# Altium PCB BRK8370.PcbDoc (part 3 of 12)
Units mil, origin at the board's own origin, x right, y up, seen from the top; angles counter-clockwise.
Board outline 8267.72 x 5708.66 mil, 6 copper layers (L1-TOP, L2-GND, L3-PWR, L4-PWR, L5-GND, L6-BOT), stack 68.606 mil thick; 319 components, 516 nets, 2008 pads, 1743 vias.
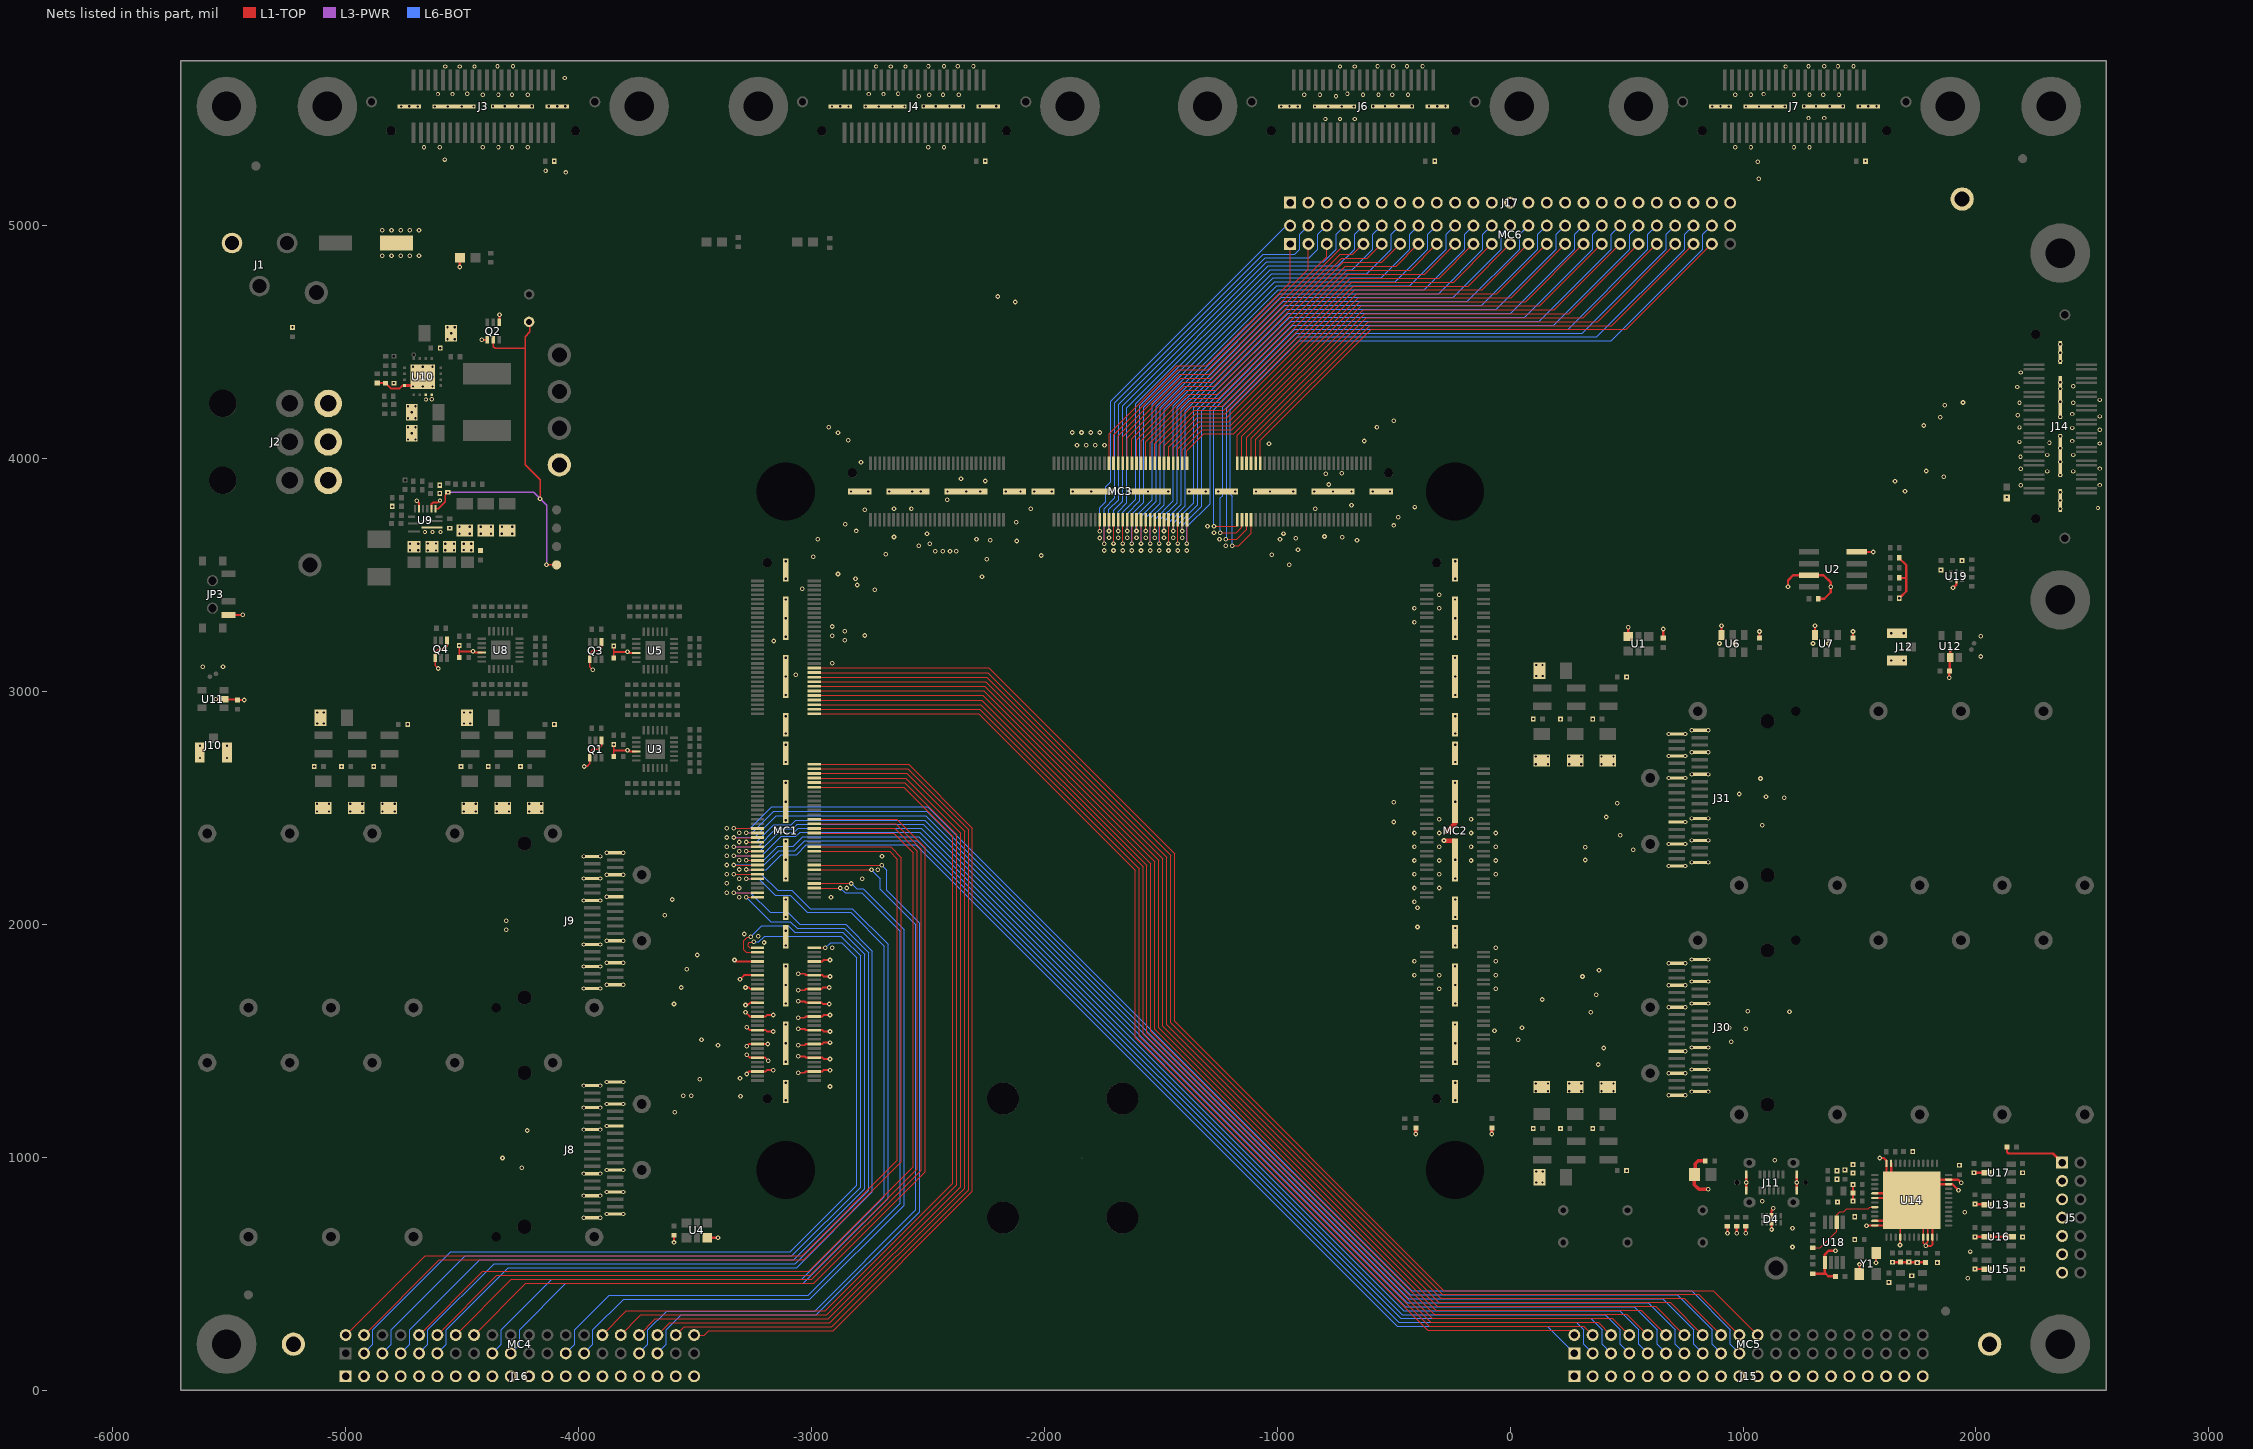
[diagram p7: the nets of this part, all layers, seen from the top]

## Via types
v1: diameter 20, hole 10, L1-TOP to L6-BOT, tented both sides, 957 vias
v2: diameter 18, hole 10, L1-TOP to L6-BOT, tented both sides, 786 vias

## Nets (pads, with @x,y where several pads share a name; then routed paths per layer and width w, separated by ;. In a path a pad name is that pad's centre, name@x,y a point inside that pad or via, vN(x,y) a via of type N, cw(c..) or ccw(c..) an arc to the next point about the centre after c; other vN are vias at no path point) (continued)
B68_L11N: MC1.96 MC4.16 | length 4145.3
  L1-TOP w4.96: MC4.16@-4448.82,236.22 -4226.79,458.25 -2991.04,458.25 -2512.19,937.1 -2512.19,2328.34 -2634.64,2450.79 -2935.44,2450.79 MC1.96@-2988.58,2450.79
B68_L11P: MC1.94 MC4.14 | length 4173.7
  L1-TOP w4.96: MC4.14@-4527.56,236.22 -4288.57,475.21 -2998.07,475.21 -2529.15,944.13 -2529.15,2321.31 -2638.94,2431.1 -2935.44,2431.1 MC1.94@-2988.58,2431.1
B68_L12N: MC1.92 MC4.12 | length 4202.2
  L1-TOP w4.96: MC4.12@-4606.3,236.22 -4350.35,492.17 -3005.09,492.17 -2546.12,951.15 -2546.12,2314.29 -2643.25,2411.42 -2935.44,2411.42 MC1.92@-2988.58,2411.42
B68_L12P: MC1.90 MC4.10 | length 4230.6
  L1-TOP w4.96: MC4.10@-4685.04,236.22 -4412.12,509.14 -3012.12,509.14 -2563.08,958.18 -2563.08,2307.26 -2647.55,2391.73 -2935.44,2391.73 MC1.90@-2988.58,2391.73
B68_L13N: MC1.84 MC4.4 | length 4315.9
  L1-TOP w4.96: MC4.4@-4921.26,236.22 -4597.46,560.02 -3033.2,560.02 -2613.97,979.26 -2613.97,2286.18 -2660.46,2332.68 -2935.44,2332.68 MC1.84@-2988.58,2332.68
B68_L13P: MC1.82 MC4.2 | length 4344.3
  L1-TOP w4.96: MC4.2@-5000,236.22 -4659.23,576.99 -3040.23,576.99 -2630.93,986.28 -2630.93,2279.15 -2664.77,2312.99 -2935.44,2312.99 MC1.82@-2988.58,2312.99
B68_L14N: MC1.91 MC5.19 | length 5468.2
  L1-TOP w4.96: v1(-3333.92,2412.11) -3333.22,2411.42 MC1.91@-3231.89,2411.42 MC1.91@-3231.62,2411.69
  L6-BOT w4.96: v1(-3333.92,2412.11) -3262.99,2412.11 -3170.83,2504.27 -2499.71,2504.27 -421.5,426.07 778.99,426.07 946.06,259.01 946.06,195.67 MC5.19@984.25,157.48
B68_L14P: MC1.89 MC5.17 | length 5273.4
  L1-TOP w4.96: v1(-3280.05,2392.54) -3279.78,2392.27 -3231.89,2392.27 MC1.89@-3231.62,2392
  L6-BOT w4.96: v1(-3280.05,2392.54) -3255,2392.54 -3162.95,2484.59 -2504.01,2484.59 -428.53,409.11 717.22,409.11 867.32,259.01 867.32,195.67 MC5.17@905.51,157.48
B68_L15N: MC1.76 MC4.35 | length 3261.7
  L1-TOP w4.96: MC1.76@-2988.58,2253.94 v1(-2698.82,2253.94)
  L6-BOT w4.96: MC4.35@-3661.42,157.48 -3623.22,195.67 -3623.22,259.01 -3559.97,322.26 -2978.59,322.26 -2534.46,766.38 -2534.46,2004.91 -2676.29,2146.73 -2676.29,2231.41 v1(-2698.82,2253.94)
B68_L15P: MC1.74 MC4.33 | length 3266.5
  L1-TOP w4.96: MC1.74@-2988.58,2234.25 -2743.38,2234.25 v1(-2742.51,2233.38)
  L6-BOT w4.96: MC4.33@-3740.16,157.48 -3701.96,195.67 -3701.96,259.01 -3621.75,339.22 -2985.61,339.22 -2551.43,773.41 -2551.43,1997.88 -2704.72,2151.18 -2704.72,2195.59 v1(-2742.51,2233.38)
B68_L16N: MC1.75 MC5.3 | length 4782.2
  L1-TOP w4.96: v1(-3333.92,2254.63) -3333.22,2253.94 MC1.75@-3231.89,2253.94 MC1.75@-3231.62,2254.21
  L6-BOT w4.96: v1(-3333.92,2254.63) -3202.06,2254.63 -3141.07,2315.63 -3070.93,2315.63 -3028.77,2357.79 -2545.13,2357.79 -477.71,290.37 284.78,290.37 316.14,259.01 316.14,195.67 MC5.3@354.33,157.48
B68_L16P: MC1.73 MC5.1 | length 4552.5
  L1-TOP w4.96: v1(-3280.05,2235.06) -3279.78,2234.79 -3231.89,2234.79 MC1.73@-3231.62,2234.52
  L6-BOT w4.96: v1(-3280.05,2235.06) -3194.07,2235.06 -3129.92,2299.21 -3064.13,2299.21 -3022.52,2340.82 -2935.44,2340.82 -2552.16,2340.82 -484.74,273.41 159.66,273.41 MC5.1@275.59,157.48
B68_L17N: MC1.63 MC4.11 | length 4029.5
  L1-TOP w4.96: v1(-3333.92,2135.98) -3333.22,2135.29 -3231.89,2135.29 MC1.63@-3231.62,2135.56
  L6-BOT w4.96: MC4.11@-4606.3,157.48 -4568.11,195.67 -4568.11,259.01 -4301.3,525.81 -3062.9,525.81 -2738.02,850.7 -2738.02,1885.16 -2852.42,1999.56 -2852.79,1999.56 -2852.94,1999.71 -3050.89,1999.71 -3102.36,2051.18 -3177.17,2051.18 -3261.97,2135.98 v1(-3333.92,2135.98)
B68_L17P: MC1.61 MC4.9 | length 3950
  L1-TOP w4.96: v1(-3280.05,2116.41) -3279.78,2116.14 MC1.61@-3231.89,2116.14 MC1.61@-3231.62,2115.87
  L6-BOT w4.96: MC4.9@-4685.04,157.48 -4646.85,195.67 -4646.85,259.01 -4363.08,542.78 -3069.93,542.78 -2754.98,857.72 -2754.98,1878.13 -2859.45,1982.59 -2859.81,1982.59 -2859.96,1982.74 -3061.48,1982.74 -3090.55,2011.81 -3175.45,2011.81 v1(-3280.05,2116.41)
B68_L18N: MC1.68 MC4.27 | length 3325.8
  L1-TOP w4.96: MC1.68@-2988.58,2175.2 v1(-2828.74,2175.2)
  L6-BOT w4.96: MC4.27@-3976.38,157.48 -3938.18,195.67 -3938.18,259.01 -3807.08,390.11 -3006.69,390.11 -2602.32,794.48 -2602.32,1976.8 -2719.3,2093.79 -2777.84,2152.33 -2805.87,2152.33 v1(-2828.74,2175.2)
B68_L18P: MC1.66 MC4.25 | length 3354.2
  L1-TOP w4.96: MC1.66@-2988.58,2155.51 v1(-2875.98,2155.51)
  L6-BOT w4.96: MC4.25@-4055.12,157.48 -4016.93,195.67 -4016.93,259.01 -3868.86,407.07 -3013.72,407.07 -2619.28,801.51 -2619.28,1969.78 -2726.33,2076.82 -2784.87,2135.37 -2855.84,2135.37 v1(-2875.98,2155.51)
B68_L19N: MC1.79 MC5.7 | length 4954.7
  L1-TOP w4.96: v1(-3333.92,2294) -3333.22,2293.31 MC1.79@-3231.89,2293.31 MC1.79@-3231.62,2293.58
  L6-BOT w4.96: v1(-3333.92,2294) -3213.87,2294 -3130.3,2377.58 -3066.97,2377.58 -3048.89,2395.65 -2535.02,2395.65 -463.66,324.3 408.33,324.3 473.62,259.01 473.62,195.67 MC5.7@511.81,157.48
B68_L19P: MC1.77 MC5.5 | length 4760.6
  L1-TOP w4.96: v1(-3280.05,2274.43) -3279.78,2274.16 -3231.89,2274.16 MC1.77@-3231.62,2273.89
  L6-BOT w4.96: v1(-3280.05,2274.43) -3205.88,2274.43 -3145.67,2334.65 -3078.81,2334.65 -3036.65,2376.81 -2540.16,2376.81 -470.69,307.33 346.69,307.33 394.88,259.15 394.88,195.67 MC5.5@433.07,157.48
B68_L20N: MC1.83 MC5.11 | length 5124
  L1-TOP w4.96: v1(-3333.92,2333.37) -3333.22,2332.68 MC1.83@-3231.89,2332.68 MC1.83@-3231.62,2332.95
  L6-BOT w4.96: v1(-3333.92,2333.37) -3229.36,2333.37 -3152.65,2410.08 -3080.43,2410.08 -3060.93,2429.58 -2520.97,2429.58 -449.61,358.22 531.88,358.22 631.1,259.01 631.1,195.67 MC5.11@669.29,157.48
B68_L20P: MC1.81 MC5.9 | length 4931.4
  L1-TOP w4.96: v1(-3280.05,2313.8) -3279.78,2313.53 -3231.89,2313.53 MC1.81@-3231.62,2313.26
  L6-BOT w4.96: v1(-3280.05,2313.8) -3221.58,2313.8 -3140.49,2394.89 -3074.14,2394.89 -3056.41,2412.62 -2527.99,2412.62 -456.64,341.26 470.11,341.26 552.36,259.01 552.36,195.67 MC5.9@590.55,157.48
B68_L22N: MC1.71 MC4.19 | length 3916
  L1-TOP w4.96: v1(-3333.92,2215.26) -3333.22,2214.57 MC1.71@-3231.89,2214.57 MC1.71@-3231.62,2214.84
  L6-BOT w4.96: MC4.19@-4291.34,157.48 -4253.15,195.67 -4253.15,259.01 -4054.19,457.96 -3034.8,457.96 -2670.17,822.59 -2670.17,1913.26 -2824.46,2067.56 -3006.3,2067.56 -3084.41,2145.67 -3145.67,2145.67 -3215.26,2215.26 v1(-3333.92,2215.26)
B68_L22P: MC1.69 MC4.17 | length 3836.6
  L1-TOP w4.96: v1(-3280.05,2195.69) -3279.78,2195.42 -3231.89,2195.42 MC1.69@-3231.62,2195.15
  L6-BOT w4.96: MC4.17@-4370.08,157.48 -4331.89,195.67 -4331.89,259.01 -4115.97,474.92 -3041.82,474.92 -2687.13,829.62 -2687.13,1906.24 -2831.49,2050.6 -3018.12,2050.6 -3091.3,2123.78 -3155.28,2123.78 -3227.19,2195.69 v1(-3280.05,2195.69)
B68_L23N: MC1.87 MC5.15 | length 5294.4
  L1-TOP w4.96: v1(-3333.92,2372.74) -3333.22,2372.05 MC1.87@-3231.89,2372.05 MC1.87@-3231.62,2372.32
  L6-BOT w4.96: v1(-3333.92,2372.74) -3243.3,2372.74 -3151.14,2464.9 -2508.31,2464.9 -2448.92,2405.51 -435.56,392.15 655.44,392.15 788.58,259.01 788.58,195.67 MC5.15@826.77,157.48
B68_L23P: MC1.85 MC5.13 | length 5100.7
  L1-TOP w4.96: v1(-3280.05,2353.17) -3279.78,2352.9 -3231.89,2352.9 MC1.85@-3231.62,2352.63
  L6-BOT w4.96: v1(-3280.05,2353.17) -3236.69,2353.17 -3162.99,2426.86 -3087.38,2426.86 -3067.7,2446.54 -2513.94,2446.54 -442.58,375.18 593.66,375.18 709.84,259.01 709.84,195.67 MC5.13@748.03,157.48
B68_T0U_N12_VRP: MC1.59 MC4.5 | length 3963.8
  L1-TOP w4.96: v1(-3247.56,1924.77) -3250,1922.32 -3266.66,1922.32 -3271.65,1917.32 -3271.65,1905.51 -3265.75,1899.61 MC1.59@-3231.89,1899.61
  L6-BOT w4.96: MC4.5@-4842.52,157.48 -4804.33,195.67 -4804.33,259.01 -4486.63,576.7 -3083.98,576.7 -2788.91,871.77 -2788.91,1864.08 -2863.05,1938.22 -2863.42,1938.22 -2874.02,1948.82 -3201.6,1948.82 -3225.65,1924.77 v1(-3247.56,1924.77)
B68_T1U_N12: MC1.57 MC4.7 | length 4027.5
  L1-TOP w4.96: v1(-3261.32,1945.8) -3262.02,1945.1 -3275.37,1945.1 -3291.3,1929.17 -3291.3,1890.71 -3280.52,1879.92 MC1.57@-3231.89,1879.92
  L6-BOT w4.96: MC4.7@-4763.78,157.48 -4725.59,195.67 -4725.59,259.01 -4424.85,559.74 -3076.95,559.74 -2771.95,864.75 -2771.95,1871.11 -2866.47,1965.63 -2866.84,1965.63 -2866.99,1965.78 -3072.08,1965.78 -3100.01,1993.71 -3213.41,1993.71 v1(-3261.32,1945.8)
B68_T2U_N12: MC1.60 MC4.3 | length 3648.6
  L1-TOP w4.96: MC1.60@-2988.85,1899.34 -2988.58,1899.07 -2940.69,1899.07 v1(-2940.42,1898.8)
  L6-BOT w4.96: MC4.3@-4921.26,157.48 -4883.07,195.67 -4883.07,259.01 -4548.41,593.67 -3091.01,593.67 -2805.87,878.8 -2805.87,1857.05 -2870.08,1921.26 -2917.96,1921.26 v1(-2940.42,1898.8)
B69_L3P: MC1.142 MC5.22 | length 5659.3
  L1-TOP w4.96: MC1.142@-2988.58,3100.39 -2238.45,3100.39 -1440.61,2302.55 -1440.61,1583.34 -284.56,427.29 871.92,427.29 MC5.22@1062.99,236.22
B69_L5N: MC1.136 MC5.16 | length 5398.6
  L1-TOP w4.96: MC1.136@-2988.58,3041.34 -2251.37,3041.34 -1491.5,2281.47 -1491.5,1562.26 -305.64,376.4 686.59,376.4 MC5.16@826.77,236.22
B69_L5P: MC1.134 MC5.14 | length 5311.7
  L1-TOP w4.96: MC1.134@-2988.58,3021.65 -2255.67,3021.65 -1508.46,2274.44 -1508.46,1555.23 -312.66,359.44 624.82,359.44 MC5.14@748.03,236.22
B69_L11N: MC1.128 MC5.8 | length 5051
  L1-TOP w4.96: MC1.128@-2988.58,2962.6 -2935.44,2962.6 -2268.58,2962.6 -1559.35,2253.36 -1559.35,1534.15 -333.74,308.55 439.48,308.55 MC5.8@511.81,236.22
B69_L11P: MC1.126 MC5.6 | length 4964.1
  L1-TOP w4.96: MC1.126@-2988.58,2942.91 -2935.44,2942.91 -2272.89,2942.91 -1576.31,2246.34 -1576.31,1527.13 -340.77,291.58 377.71,291.58 MC5.6@433.07,236.22
B69_L14N: MC1.112 MC4.32 | length 3917.9
  L1-TOP w4.96: MC4.32@-3818.9,236.22 -3732.58,322.54 -2934.83,322.54 -2376.49,880.89 -2376.49,2384.55 -2600.2,2608.27 -2935.44,2608.27 MC1.112@-2988.58,2608.27
B69_L14P: MC1.110 MC4.30 | length 3946.3
  L1-TOP w4.96: MC4.30@-3897.64,236.22 -3794.35,339.51 -2941.86,339.51 -2393.45,887.91 -2393.45,2377.52 -2604.51,2588.58 -2935.44,2588.58 MC1.110@-2988.58,2588.58
B69_L16N: MC1.116 MC4.36 | length 3861
  L1-TOP w4.96: MC4.36@-3661.42,236.22 -3609.02,288.62 -2920.78,288.62 -2342.56,866.84 -2342.56,2398.6 -2591.6,2647.64 -2935.44,2647.64 MC1.116@-2988.58,2647.64
B69_L16P: MC1.114 MC4.34 | length 3889.4
  L1-TOP w4.96: MC4.34@-3740.16,236.22 -3670.8,305.58 -2927.81,305.58 -2359.52,873.86 -2359.52,2391.58 -2595.9,2627.95 -2935.44,2627.95 MC1.114@-2988.58,2627.95
B69_L20N: MC1.140 MC5.20 | length 5572.4
  L1-TOP w4.96: MC1.140@-2988.58,3080.71 -2242.76,3080.71 -1457.57,2295.52 -1457.57,1576.31 -291.58,410.33 810.15,410.33 MC5.20@984.25,236.22
B69_L20P: MC1.138 MC5.18 | length 5485.5
  L1-TOP w4.96: MC1.138@-2988.58,3061.02 -2247.06,3061.02 -1474.53,2288.49 -1474.53,1569.29 -298.61,393.36 748.37,393.36 MC5.18@905.51,236.22
B69_L21N: MC1.124 MC5.4 | length 4877.2
  L1-TOP w4.96: MC1.124@-2988.58,2923.23 -2935.44,2923.23 -2277.19,2923.23 -1593.27,2239.31 -1593.27,1520.1 -347.79,274.62 315.93,274.62 MC5.4@354.33,236.22
B69_L21P: MC1.122 MC5.2 | length 4790.3
  L1-TOP w4.96: MC1.122@-2988.58,2903.54 -2935.44,2903.54 -2281.5,2903.54 -1610.24,2232.28 -1610.24,1513.07 -354.82,257.66 254.15,257.66 MC5.2@275.59,236.22
B69_L23N: MC1.120 MC4.40 | length 3804.2
  L1-TOP w4.96: MC4.40@-3503.94,236.22 -3460.63,236.22 -3442.16,254.69 -2906.73,254.69 -2308.63,852.78 -2308.63,2412.65 -2582.99,2687.01 -2935.44,2687.01 MC1.120@-2988.58,2687.01
B69_L23P: MC1.118 MC4.38 | length 3832.6
  L1-TOP w4.96: MC4.38@-3582.68,236.22 -3547.24,271.65 -2913.75,271.65 -2325.6,859.81 -2325.6,2405.63 -2587.29,2667.32 -2935.44,2667.32 MC1.118@-2988.58,2667.32
B69_L24N: MC1.132 MC5.12 | length 5224.8
  L1-TOP w4.96: MC1.132@-2988.58,3001.97 -2259.98,3001.97 -1525.42,2267.41 -1525.42,1548.21 -319.69,342.47 563.04,342.47 MC5.12@669.29,236.22
B69_L24P: MC1.130 MC5.10 | length 5137.9
  L1-TOP w4.96: MC1.130@-2988.58,2982.28 -2264.28,2982.28 -1542.38,2260.39 -1542.38,1541.18 -326.71,325.51 501.26,325.51 MC5.10@590.55,236.22
B88_L1N: MC3.104 MC6.24 | length 2475
  L1-TOP w4.96: v1(-1545.43,3634.59) -1544.74,3635.28 -1544.74,3736.61 MC3.104@-1545.01,3736.88
  L6-BOT w4.96: v1(-1545.43,3634.59) -1545.43,3742.34 -1485.99,3801.78 -1485.99,4211.13 -1310.17,4386.95 -988.79,4708.32 -323.65,4708.32 -307.08,4708.32 -116.93,4898.47 -116.93,4961.81 MC6.24@-78.74,5000
B88_L1P: MC3.102 MC6.22 | length 2310.6
  L1-TOP w4.96: v1(-1565.23,3688.45) -1564.96,3688.72 MC3.102@-1564.96,3736.61 MC3.102@-1564.69,3736.88
  L6-BOT w4.96: v1(-1565.23,3688.45) -1565.23,3746.53 -1502.95,3808.81 -1502.95,4218.16 -995.82,4725.29 -385.42,4725.29 -368.86,4725.29 -195.67,4898.47 -195.67,4961.81 MC6.22@-157.48,5000
B88_L2N: MC3.87 MC6.3 | length 1362.4
  L1-TOP w4.96: MC3.87@-1702.76,3979.92 -1702.76,4055.12 -1702.76,4102.33 -1425.04,4380.05 -1297.85,4380.05 -866.14,4811.76 MC6.3@-866.14,4921.26
B88_L2P: MC3.85 MC6.1 | length 1337.9
  L1-TOP w4.96: MC3.85@-1722.44,3979.92 -1722.44,4055.12 -1722.44,4106.64 -1431.44,4397.64 -1304.25,4397.64 -944.88,4757.01 MC6.1@-944.88,4921.26
B88_L3N: MC3.103 MC6.19 | length 1750.5
  L1-TOP w4.96: MC3.103@-1545.28,3979.92 -1545.28,4067.9 -1371.17,4242 -1243.98,4242 -694.56,4791.43 -366.05,4791.43 MC6.19@-236.22,4921.26
B88_L3P: MC3.101 MC6.17 | length 1694
  L1-TOP w4.96: MC3.101@-1564.96,3979.92 -1564.96,4072.2 -1378.2,4258.97 -1251.01,4258.97 -701.59,4808.39 -427.83,4808.39 MC6.17@-314.96,4921.26
B88_L4N: MC3.95 MC6.11 | length 1524.4
  L1-TOP w4.96: MC3.95@-1624.02,3979.92 -1624.02,4085.12 -1399.28,4309.86 -1272.09,4309.86 -722.66,4859.28 -613.16,4859.28 MC6.11@-551.18,4921.26
B88_L4P: MC3.93 MC6.9 | length 1467.8
  L1-TOP w4.96: MC3.93@-1643.7,3979.92 -1643.7,4055.12 -1643.7,4089.42 -1406.3,4326.82 -1279.11,4326.82 -729.69,4876.24 -674.94,4876.24 MC6.9@-629.92,4921.26
B88_L5N: MC3.99 MC6.15 | length 1637.4
  L1-TOP w4.96: MC3.99@-1584.65,3979.92 -1584.65,4076.51 -1385.22,4275.93 -1258.03,4275.93 -708.61,4825.35 -489.61,4825.35 MC6.15@-393.7,4921.26
B88_L5P: MC3.97 MC6.13 | length 1569.8
  L1-TOP w4.96: MC3.97@-1601.61,3992.13 -1604.33,3994.85 -1604.33,4080.81 -1392.25,4292.89 -1265.06,4292.89 -715.64,4842.32 -551.39,4842.32 MC6.13@-472.44,4921.26
B88_L6N: MC3.91 MC6.7 | length 1411.3
  L1-TOP w4.96: MC3.91@-1663.39,3979.92 -1663.39,4055.12 -1663.39,4093.72 -1413.33,4343.78 -1286.14,4343.78 MC6.7@-708.66,4921.26
B88_L6P: MC3.89 MC6.5 | length 1386.8
  L1-TOP w4.96: MC3.89@-1683.07,3979.92 -1683.07,4055.12 -1683.07,4098.03 -1418.89,4362.2 -1291.71,4362.2 -787.4,4866.51 MC6.5@-787.4,4921.26
B88_L7N: MC3.84 MC6.4 | length 1910
  L1-TOP w4.96: v1(-1742.55,3634.32) -1741.86,3635.01 -1741.86,3736.34 MC3.84@-1742.13,3736.61
  L6-BOT w4.96: v1(-1742.55,3634.32) -1742.55,3785.11 -1697.15,3830.52 -1697.15,4239.86 -1059.06,4877.95 -924.86,4877.95 -904.33,4898.47 -904.33,4961.81 MC6.4@-866.14,5000
B88_L7P: MC3.82 MC6.2 | length 1708.5
  L1-TOP w4.96: v1(-1762.35,3688.18) -1762.08,3688.45 -1762.08,3736.34 MC3.82@-1761.81,3736.61
  L6-BOT w4.96: v1(-1762.35,3688.18) -1762.35,3789.3 -1736.57,3815.08 -1736.57,3879.22 -1714.65,3901.14 -1714.65,4055.12 -1714.65,4246.34 -969.84,4991.16 -953.73,4991.16 MC6.2@-944.88,5000
B88_L8N: MC3.107 MC6.23 | length 1863.6
  L1-TOP w4.96: MC3.107@-1505.91,3979.92 -1505.91,4059.29 -1357.12,4208.08 -1229.93,4208.08 -680.51,4757.5 -242.5,4757.5 MC6.23@-78.74,4921.26
B88_L8P: MC3.105 MC6.21 | length 1807
  L1-TOP w4.96: MC3.105@-1525.59,3979.92 -1525.59,4063.59 -1364.14,4225.04 -1236.96,4225.04 -687.53,4774.46 -304.28,4774.46 MC6.21@-157.48,4921.26
B88_L9N: MC3.92 MC6.12 | length 2135.8
  L1-TOP w4.96: v1(-1663.54,3634.59) -1662.85,3635.28 -1662.85,3736.61 MC3.92@-1663.12,3736.88
  L6-BOT w4.96: v1(-1663.54,3634.59) -1663.54,3768.16 -1606.53,3825.18 -1606.53,4234.52 -1030.95,4810.1 -677.75,4810.1 -589.37,4898.47 -589.37,4961.81 MC6.12@-551.18,5000
B88_L9P: MC3.90 MC6.10 | length 1971.4
  L1-TOP w4.96: v1(-1683.34,3688.45) -1683.07,3688.72 MC3.90@-1683.07,3736.61 MC3.90@-1682.8,3736.88
  L6-BOT w4.96: v1(-1683.34,3688.45) -1683.34,3772.35 -1646.26,3809.44 -1646.26,4218.78 -1037.98,4827.06 -739.52,4827.06 -668.11,4898.47 -668.11,4961.81 MC6.10@-629.92,5000
B88_L10N: MC3.96 MC6.16 | length 2248.8
  L1-TOP w4.96: v1(-1624.17,3634.59) -1623.48,3635.28 -1623.48,3736.61 MC3.96@-1623.75,3736.88
  L6-BOT w4.96: v1(-1624.17,3634.59) -1624.17,3759.55 -1572.6,3811.13 -1572.6,4220.47 -1016.9,4776.17 -554.19,4776.17 -431.89,4898.47 -431.89,4961.81 MC6.16@-393.7,5000
B88_L10P: MC3.94 MC6.14 | length 2084.4
  L1-TOP w4.96: v1(-1643.97,3688.45) -1643.7,3688.72 MC3.94@-1643.7,3736.61 MC3.94@-1643.43,3736.88
  L6-BOT w4.96: v1(-1643.97,3688.45) -1643.97,3763.75 -1589.56,3818.15 -1589.56,4227.5 -1023.92,4793.14 -615.97,4793.14 -510.63,4898.47 -510.63,4961.81 MC6.14@-472.44,5000
B88_L11N: MC3.88 MC6.8 | length 2022.7
  L1-TOP w4.96: v1(-1702.91,3634.59) -1702.22,3635.28 -1702.22,3736.61 MC3.88@-1702.49,3736.88
  L6-BOT w4.96: v1(-1702.91,3634.59) -1702.91,3776.77 -1663.22,3816.46 -1663.22,4225.81 -1045,4844.03 -801.3,4844.03 -746.85,4898.47 -746.85,4961.81 MC6.8@-708.66,5000
B88_L11P: MC3.86 MC6.6 | length 1858.3
  L1-TOP w4.96: v1(-1722.71,3688.45) -1722.44,3688.72 MC3.86@-1722.44,3736.61 MC3.86@-1722.17,3736.88
  L6-BOT w4.96: v1(-1722.71,3688.45) -1722.71,3780.96 -1680.18,3823.49 -1680.18,4232.84 -1052.03,4860.99 -863.08,4860.99 -825.59,4898.47 -825.59,4961.81 MC6.6@-787.4,5000
B88_L12N: MC3.100 MC6.20 | length 2361.9
  L1-TOP w4.96: v1(-1584.8,3634.59) -1584.11,3635.28 -1584.11,3736.61 MC3.100@-1584.38,3736.88
  L6-BOT w4.96: v1(-1584.8,3634.59) -1584.8,3750.95 -1519.91,3815.84 -1519.91,4225.18 -1002.84,4742.25 -430.64,4742.25 -274.41,4898.47 -274.41,4961.81 MC6.20@-236.22,5000
B88_L12P: MC3.98 MC6.18 | length 2197.5
  L1-TOP w4.96: v1(-1604.6,3688.45) -1604.33,3688.72 MC3.98@-1604.33,3736.61 MC3.98@-1604.06,3736.88
  L6-BOT w4.96: v1(-1604.6,3688.45) -1604.6,3755.14 -1536.87,3822.86 -1536.87,4232.21 -1009.87,4759.21 -492.42,4759.21 -353.15,4898.47 -353.15,4961.81 MC6.18@-314.96,5000
B89_L1N: MC3.112 MC6.32 | length 2701.1
  L1-TOP w4.96: v1(-1466.69,3634.59) -1466,3635.28 -1466,3736.61 MC3.112@-1466.27,3736.88
  L6-BOT w4.96: v1(-1466.69,3634.59) -1466.69,3725.12 -1395.43,3796.38 -1395.43,4205.72 -1315.63,4285.53 -960.69,4640.47 -76.54,4640.47 -59.97,4640.47 198.03,4898.47 198.03,4961.81 MC6.32@236.22,5000
B89_L1P: MC3.110 MC6.30 | length 2536.7
  L1-TOP w4.96: v1(-1486.49,3688.45) -1486.22,3688.72 MC3.110@-1486.22,3736.61 MC3.110@-1485.95,3736.88
  L6-BOT w4.96: v1(-1486.49,3688.45) -1486.49,3729.31 -1412.4,3803.4 -1412.4,4212.75 -1335.82,4289.33 -1274.18,4350.97 -967.71,4657.43 -138.31,4657.43 -121.75,4657.43 119.29,4898.47 119.29,4961.81 MC6.30@157.48,5000
B89_L2N: MC3.108 MC6.28 | length 2588
  L1-TOP w4.96: v1(-1506.06,3634.59) -1505.37,3635.28 -1505.37,3736.61 MC3.108@-1505.64,3736.88
  L6-BOT w4.96: v1(-1506.06,3634.59) -1506.06,3733.73 -1429.36,3810.43 -1429.36,4219.78 -1348.81,4300.33 -974.74,4674.4 -200.09,4674.4 -183.53,4674.4 40.55,4898.47 40.55,4961.81 MC6.28@78.74,5000
B89_L2P: MC3.106 MC6.26 | length 2423.6
  L1-TOP w4.96: v1(-1525.86,3688.45) -1525.59,3688.72 MC3.106@-1525.59,3736.61 MC3.106@-1525.32,3736.88
  L6-BOT w4.96: v1(-1525.86,3688.45) -1525.86,3737.92 -1446.32,3817.46 -1446.32,4226.8 -1353.37,4319.76 -981.77,4691.36 -261.87,4691.36 -245.31,4691.36 -38.19,4898.47 -38.19,4961.81 MC6.26@0,5000
B89_L3N: MC3.116 MC6.36 | length 2814.2
  L1-TOP w4.96: v1(-1427.32,3634.59) -1426.63,3635.28 -1426.63,3736.61 MC3.116@-1426.9,3736.88
  L6-BOT w4.96: v1(-1427.32,3634.59) -1427.32,3716.51 -1341.53,3802.3 -1341.53,4211.65 -1256.83,4296.35 -946.63,4606.54 63.58,4606.54 355.51,4898.47 355.51,4961.81 MC6.36@393.7,5000
B89_L3P: MC3.114 MC6.34 | length 2649.8
  L1-TOP w4.96: v1(-1447.12,3688.45) -1446.85,3688.72 MC3.114@-1446.85,3736.61 MC3.114@-1446.58,3736.88
  L6-BOT w4.96: v1(-1447.12,3688.45) -1444.42,3691.15 -1444.42,3723.4 -1358.49,3809.33 -1358.49,4218.67 -1281.32,4295.84 -953.66,4623.51 -14.76,4623.51 1.8,4623.51 276.77,4898.47 276.77,4961.81 MC6.34@314.96,5000
B89_L4N: MC3.120 MC6.40 | length 2927.2
  L1-TOP w4.96: v1(-1387.95,3634.59) -1387.26,3635.28 -1387.26,3736.61 MC3.120@-1387.53,3736.88
  L6-BOT w4.96: v1(-1387.95,3634.59) -1387.95,3706.54 -1288.62,3805.87 -1288.62,4216.58 -932.58,4572.62 170.57,4572.62 187.13,4572.62 512.99,4898.47 512.99,4961.81 MC6.40@551.18,5000
B89_L4P: MC3.118 MC6.38 | length 2762.8
  L1-TOP w4.96: v1(-1407.75,3688.45) -1407.48,3688.72 MC3.118@-1407.48,3736.61 MC3.118@-1407.21,3736.88
  L6-BOT w4.96: v1(-1407.75,3688.45) -1407.75,3711.36 -1324.57,3794.54 -1324.57,4204.62 -939.61,4589.58 108.79,4589.58 125.36,4589.58 434.25,4898.47 434.25,4961.81 MC6.38@472.44,5000
B89_L5N: MC3.128 MC6.48 | length 3177.3
  L1-TOP w4.96: v1(-1192.91,3625.98) -1166.21,3625.98 -1112.2,3679.99 MC3.128@-1112.2,3736.61
  L6-BOT w4.96: v1(-1192.91,3625.98) -1192.91,3838.58 -1200.79,3846.46 -1200.79,4208.46 -904.48,4504.77 434.24,4504.77 827.95,4898.47 827.95,4961.81 MC6.48@866.14,5000
B89_L5P: MC3.126 MC6.46 | length 3077
  L1-TOP w4.96: v1(-1220.47,3653.54) -1174.39,3653.54 -1131.89,3696.04 MC3.126@-1131.89,3736.61
  L6-BOT w4.96: v1(-1220.47,3653.54) -1217.75,3656.27 -1217.75,4215.48 -1178.22,4255.01 -911.5,4521.73 372.47,4521.73 749.21,4898.47 749.21,4961.81 MC6.46@787.4,5000
B89_L6N: MC3.127 MC6.43 | length 2272.9
  L1-TOP w4.96: MC3.127@-1112.2,3979.92 -1112.2,4085.91 -610.24,4587.87 375.27,4587.87 MC6.43@708.66,4921.26
B89_L6P: MC3.125 MC6.41 | length 2216.3
  L1-TOP w4.96: MC3.125@-1131.89,3979.92 -1131.89,4090.21 -617.27,4604.83 313.49,4604.83 MC6.41@629.92,4921.26
B89_L7N: MC3.115 MC6.31 | length 2089.7
  L1-TOP w4.96: MC3.115@-1427.17,3979.92 -1427.17,4042.07 -1414.12,4055.12 -1329.01,4140.23 -1201.82,4140.23 -652.4,4689.65 4.61,4689.65 MC6.31@236.22,4921.26
B89_L7P: MC3.113 MC6.29 | length 2033.2
  L1-TOP w4.96: MC3.113@-1446.85,3979.92 -1446.85,4046.38 -1438.11,4055.12 -1336.04,4157.19 -1208.85,4157.19 -659.43,4706.61 -57.17,4706.61 MC6.29@157.48,4921.26
B89_L8N: MC3.119 MC6.35 | length 2202.8
  L1-TOP w4.96: MC3.119@-1387.8,3979.92 -1387.8,4033.46 -1366.14,4055.12 -1314.96,4106.3 -1187.77,4106.3 -638.35,4655.72 128.16,4655.72 MC6.35@393.7,4921.26
B89_L8P: MC3.117 MC6.33 | length 2146.2
  L1-TOP w4.96: MC3.117@-1407.48,3979.92 -1407.48,4037.77 -1390.13,4055.12 -1321.99,4123.26 -1194.8,4123.26 -645.37,4672.69 66.39,4672.69 MC6.33@314.96,4921.26
B89_L9N: MC3.131 MC6.47 | length 2385.9
  L1-TOP w4.96: MC3.131@-1072.83,3979.92 -1072.83,4077.3 -596.19,4553.94 498.83,4553.94 MC6.47@866.14,4921.26
B89_L9P: MC3.129 MC6.45 | length 2329.4
  L1-TOP w4.96: MC3.129@-1092.52,3979.92 -1092.52,4081.6 -603.22,4570.91 437.05,4570.91 MC6.45@787.4,4921.26
B89_L10N: MC3.123 MC6.39 | length 2159.8
  L1-TOP w4.96: MC3.123@-1151.58,3979.92 -1151.58,4094.52 -624.3,4621.8 251.72,4621.8 MC6.39@551.18,4921.26
B89_L10P: MC3.121 MC6.37 | length 2103.3
  L1-TOP w4.96: MC3.121@-1171.26,3979.92 -1171.26,4098.82 -631.32,4638.76 189.94,4638.76 MC6.37@472.44,4921.26
B89_L11N: MC3.111 MC6.27 | length 1976.6
  L1-TOP w4.96: MC3.111@-1466.54,3979.92 -1466.54,4050.68 -1462.1,4055.12 -1343.07,4174.15 -1215.88,4174.15 -666.45,4723.57 -118.95,4723.57 MC6.27@78.74,4921.26
B89_L11P: MC3.109 MC6.25 | length 1920.1
  L1-TOP w4.96: MC3.109@-1486.22,3979.92 -1486.22,4054.99 -1486.09,4055.12 -1350.09,4191.11 -1222.9,4191.11 -673.48,4740.54 -180.72,4740.54 MC6.25@0,4921.26
B89_L12N: MC3.124 MC6.44 | length 2981.9
  L1-TOP w4.96: v1(-1244.09,3681.1) -1175.45,3681.1 -1151.58,3704.98 MC3.124@-1151.58,3736.61
  L6-BOT w4.96: v1(-1244.09,3681.1) -1244.09,3830.71 -1234.71,3840.09 -1234.71,4222.51 -918.53,4538.69 310.69,4538.69 670.47,4898.47 670.47,4961.81 MC6.44@708.66,5000
B89_L12P: MC3.122 MC6.42 | length 2892.2
  L1-TOP w4.96: v1(-1271.65,3708.66) -1176.58,3708.66 -1171.26,3713.98 MC3.122@-1171.26,3736.61
  L6-BOT w4.96: v1(-1271.65,3708.66) -1271.65,4209.56 -925.56,4555.66 232.35,4555.66 248.91,4555.66 591.73,4898.47 591.73,4961.81 MC6.42@629.92,5000
BRK8370_PGOOD: Q2.5 R72.1 TP18.1 TP22.1 U9.7 | length 1810.9
  L1-TOP w6: U9.7@-4614.32,3784.66 -4603.07,3784.66 -4572.65,3815.08 -4572.65,3842.49 -4569.65,3845.49 -4569.65,3847.46 -4562.81,3854.3 v2(-4560.84,3854.3) ; Q2.5@-4366.14,4509.84 -4366.14,4480.32 -4358.27,4472.44 -4228.35,4472.44 ; TP22.1@-4212.6,4586.61 -4208.66,4582.68 -4208.66,4543.31 -4228.35,4523.62 -4228.35,4472.44 ; v1(-4165.42,3826.67) -4165.42,3909.52 -4228.35,3972.44 -4228.35,4472.44 ; v1(-4137.8,3543.31) TP18.1@-4094.49,3543.31
  L3-PWR w6: v2(-4560.84,3854.3) -4193.05,3854.3 -4137.8,3799.04 v1(-4137.8,3543.31)
DGND: C1.2 C2.2 C3.1 C4.1 C5.1 C6.1 C7.1 C8.1 C9.1 C10.1 C11.1 C12.1 C13.1 C14.1 C15.1 C16.1 C17.1 C18.1 C19.1 C20.1 C21.1 C22.1 C23.1 C24.1 C25.1 C26.1 C27.1 C28.2 C29.1 C30.1 C31.1 C32.1 C33.1 C34.1 C35.1 C36.1 C37.1 C38.1 C41.1 C42.1 C43.1 C44.1 C45.1 C46.1 C47.1 C48.1 C49.1 C50.1 C51.1 C52.1 C55.1 C56.1 C57.1 C58.1 C59.1 C60.1 C61.1 C62.1 C63.1 C64.1 C65.1 C66.1 C67.1 C68.1 C69.1 C70.1 C71.1 C72.1 C73.1 C74.1 C75.1 C76.1 C77.1 C78.1 C79.1 C80.1 C81.1 C82.1 C90.1 C91.1 C92.1 C93.1 C94.1 C95.1 C102.1 C103.1 C104.1 C105.1 C106.1 C107.1 C111.1 C112.1 C113.1 C114.1 C128.1 C129.1 D1.1 D4.3 D4.8 FB4.2 J1.2 J2.4 J2.5 J2.6 J3.0 J4.0 J5.1 J5.3 J5.5 J5.7 J5.9 J5.11 J5.13 J6.0 J7.0 J8.1 J8.4 J8.7 J8.13 J8.16 J8.19 J8.20 J8.23 J8.26 J8.32 J8.35 J8.38 J9.1 J9.4 J9.7 J9.13 J9.16 J9.19 J9.20 J9.23 J9.26 J9.32 J9.35 J9.38 J10.2 J11.A1 J11.A12 J11.B1 J11.B12 J12.2 J14.0 J15.1 J15.2 J15.3 J15.4 J15.5 J15.6 J15.7 J15.8 J15.9 J15.10 J15.11 J15.12 J15.13 J15.14 J15.15 J15.16 J15.17 J15.18 J15.19 J15.20 J16.1 J16.2 J16.3 J16.4 J16.5 J16.6 J16.7 J16.8 J16.9 J16.10 J16.11 J16.12 J16.13 J16.14 J16.15 J16.16 J16.17 J16.18 J16.19 J16.20 J17.1 J17.2 J17.3 J17.4 J17.5 J17.6 J17.7 J17.8 J17.9 J17.10 J17.11 J17.12 J17.13 J17.14 J17.15 J17.16 J17.17 J17.18 J17.19 J17.20 J17.21 J17.22 J17.23 J17.24 J17.25 J30.1 J30.4 J30.7 J30.13 J30.16 J30.19 J30.20 J30.23 J30.26 J30.32 J30.35 J30.38 J31.1 J31.4 J31.7 J31.13 J31.16 J31.19 J31.20 J31.23 J31.26 J31.32 J31.35 J31.38 JP3.3 MC1.0 MC1.5 MC1.6 MC1.11 MC1.12 MC1.17 MC1.18 MC1.23 MC1.24 MC1.29 MC1.30 MC1.35 MC1.36 MC1.41 MC1.42 MC1.47 MC1.48 MC1.53 MC1.54 MC2.0 MC3.0 MC6.50 Q1.1 Q1.4 Q2.1 Q2.4 Q3.1 Q3.4 Q4.1 Q4.4 R7.1 R8.1 R9.1 R10.1 R11.1 R27.1 R66.1 R67.1 R70.1 R73.1 R78.1 R93.1 R94.2 R95.1 R97.2 R98.2 R99.2 R101.1 TP10.1 TP11.1 TP12.1 TP13.1 U1.3 U2.4 U2.7 U3.22 U4.3 U5.22 U6.3 U7.3 U8.22 U9.4 U9.8 U9.11 U10.4 U10.7 U10.8 U10.PAD U11.2 U12.2 U13.2 U14.4 U14.9 U14.10 U14.11 U14.22 U14.23 U14.35 U14.36 U14.41 U14.42 U14.47 U14.48 U14.PAD U15.2 U16.2 U16.5 U17.2 U18.5 U19.4 Y1.2 Y1.4 | length 8566.2
  L1-TOP w7: v1(-4602.36,3098.43) -4616.14,3112.2 Q4.4@-4616.14,3143.7 -4616.14,3167.32 -4602.36,3181.1 -4578.74,3181.1 -4564.96,3194.88 Q4.1@-4564.96,3218.5 ; v1(-3976.38,2677.17) -3974.79,2678.76 -3962.98,2678.76 -3952.76,2688.98 -3952.76,2738.19 -3938.98,2751.97 -3915.35,2751.97 -3901.57,2765.75 Q1.1@-3901.57,2789.37 ; v1(-3938.98,3092.52) -3952.76,3106.3 Q3.4@-3952.76,3137.8 -3952.76,3161.42 -3938.98,3175.2 -3915.35,3175.2 -3901.57,3188.98 Q3.1@-3901.57,3212.6
  L1-TOP w8: JP3.3@-5502.23,3328.48 v1@-5443.36,3328.48 ; R78.1@-4865.25,4324.18 C55.1@-4829.65,4324.18 ; C55.1@-4829.25,4323.79 C55.1@-4828.86,4323.39 -4805.33,4299.87 -4770.02,4299.87 -4756.89,4312.99 U10.4@-4747.05,4312.99 ; C32.1@-4512.2,3145.67 -4512.2,3171.26 ; v1(-4512.2,3196.85) -4512.2,3171.26 ; v1(-4415.98,4509.39) -4392.18,4509.39 Q2.4@-4391.73,4509.84 ; U8.22@-4415.35,3167.32 -4445.81,3167.32 -4450.21,3171.72 v1(-4453.46,3171.72) -4511.75,3171.72 -4512.2,3171.26 ; Q2.1@-4340.55,4584.65 -4340.2,4585 -4340.2,4616.99 v1(-4339.85,4617.34) ; C5.1@-3848.82,2720.47 -3848.82,2746.06 ; v1(-3848.82,2771.65) -3848.82,2746.06 ; C30.1@-3848.82,3143.7 -3848.82,3169.29 ; v1(-3848.82,3194.88) -3848.82,3169.29 ; U3.22@-3751.97,2742.13 -3782.43,2742.13 -3786.83,2746.52 v1(-3790.07,2746.52) -3848.36,2746.52 -3848.82,2746.06 ; U5.22@-3751.97,3165.35 -3782.43,3165.35 -3786.83,3169.75 v1(-3790.07,3169.75) -3848.36,3169.75 -3848.82,3169.29 ; v1(-3330.71,1846.46) -3324.8,1840.55 MC1.53@-3231.89,1840.55 ; v1(-3307.09,1763.78) -3289.37,1781.5 MC1.47@-3231.89,1781.5 ; v1(-3283.46,1622.05) -3265.75,1604.33 -3196.67,1604.33 -3190.97,1610.04 v1(-3163.56,1610.04) ; v1(-3283.46,1653.54) -3281.17,1655.84 -3270.52,1655.84 -3262.97,1663.39 MC1.35@-3231.89,1663.39 ; v1(-3283.46,1728.35) -3268.88,1728.35 -3262.97,1722.44 MC1.41@-3231.89,1722.44 ; v1(-3278.24,1356.98) -3267.11,1368.11 MC1.5@-3231.89,1368.11 -3196.67,1368.11 -3190.97,1373.82 v1(-3163.56,1373.82) ; v1@-3278.24,1475.09 -3267.11,1486.22 MC1.17@-3231.89,1486.22 -3231.62,1485.95 -3187.41,1485.95 v1(-3187.14,1485.68) ; v1(-3278.09,1439.5) -3265.75,1427.17 MC1.11@-3231.89,1427.17 -3198.82,1427.17 v1(-3185.04,1413.39) ; v1@-3277.68,1557.21 -3265.75,1545.28 MC1.23@-3231.89,1545.28 -3196.67,1545.28 -3190.97,1539.57 v1(-3163.56,1539.57) ; v1(-3056.92,1362.4) -3029.51,1362.4 -3023.8,1368.11 MC1.6@-2988.58,1368.11 -2953.37,1368.11 -2947.66,1373.82 v1(-2920.25,1373.82) ; v1(-3056.92,1432.87) -3029.51,1432.87 -3023.8,1427.17 MC1.12@-2988.58,1427.17 -2953.37,1427.17 -2947.66,1421.46 v1(-2920.25,1421.46) ; v1(-3056.92,1480.51) -3029.51,1480.51 -3023.8,1486.22 MC1.18@-2988.58,1486.22 -2953.37,1486.22 -2947.66,1491.93 v1(-2920.25,1491.93) ; v1(-3056.92,1550.98) -3029.51,1550.98 -3023.8,1545.28 MC1.24@-2988.58,1545.28 -2953.37,1545.28 -2947.66,1539.57 v1(-2920.25,1539.57) ; v1(-3056.92,1598.62) -3029.51,1598.62 -3023.8,1604.33 MC1.30@-2988.58,1604.33 -2953.37,1604.33 -2947.66,1610.04 v1(-2920.25,1610.04) ; v1(-3056.92,1669.09) -3029.51,1669.09 -3023.8,1663.39 MC1.36@-2988.58,1663.39 ; v1(-3056.92,1716.73) -3029.51,1716.73 -3023.8,1722.44 MC1.42@-2988.58,1722.44 -2957.5,1722.44 -2951.79,1728.15 v1(-2924.38,1728.15) ; v1(-3056.92,1787.2) -3029.51,1787.2 -3023.8,1781.5 MC1.48@-2988.58,1781.5 -2953.37,1781.5 -2947.66,1775.79 v1(-2920.25,1775.79) ; MC1.36@-2992.72,1663.39 -2957.5,1663.39 -2951.79,1657.68 v1(-2924.38,1657.68) ; MC1.54@-2988.58,1840.55 -2953.37,1840.55 -2947.66,1846.26 v1(-2920.25,1846.26) ; v1(1673.8,622.47) 1674.84,623.52 1674.84,656.14 U14.4@1675.2,656.5 U14.PAD@1675.2,765.75 ; U14.PAD@1724.41,814.96 U14.PAD@1773.62,765.75 ; U14.PAD@1773.62,765.75 U14.PAD@1793.31,746.06 ; U14.PAD@1773.62,765.75 U14.9@1773.62,656.5 1773.62,631.33 v1(1785.05,619.9) ; v1(1785.05,619.9) 1787.35,622.19 1787.35,630.23 1793.31,636.19 U14.10@1793.31,656.5 U14.PAD@1793.31,746.06 ; v1(1785.05,619.9) 1786.84,618.11 1807.09,618.11 1812.99,624.02 U14.11@1812.99,656.5 1812.99,726.38 U14.PAD@1793.31,746.06
  L1-TOP w9: v1(-4694.7,3818.87) -4694.7,3817.37 -4685.19,3807.87 U9.11@-4685.19,3784.66 ; U9.8@-4632.04,3784.66 -4632.04,3804.24 -4624.76,3811.53 -4603.23,3811.53 v2(-4595.17,3819.59)
  L1-TOP w10: v1(-5558.21,2966.57) U11.2@-5522.77,2966.57 -5521,2964.8 -5465.49,2964.8 -5463.52,2962.83 -5436.35,2962.83 v1(-5436.16,2962.63) ; C55.1@-4829.65,4324.18 C55.1@-4829.25,4323.79 ; D1.1@-4509.84,4862.2 D1.1@-4509.84,4862.2 v1(-4509.78,4822.42) ; v1(-3590.55,633.86) C34.1@-3590.55,664.57 ; U4.3@-3447.83,653.54 v1(-3401.57,653.54) ; U1.3@506.89,3236.22 v1(506.89,3275.59) ; C6.1@657.48,3228.74 v1(657.48,3268.11) ; U6.3@907.48,3242.13 v1(907.48,3281.5) ; v1(933.07,673.23) R97.2@933.07,702.76 ; v1(972.44,673.23) R98.2@972.44,702.76 ; v1(1011.81,673.23) R99.2@1011.81,702.76 ; J11.A12@1013.78,856.89 J11.B1@1013.78,925 ; C51.1@1070.87,3228.74 v1(1070.87,3256.8) ; D4.8@1122.05,717.22 1122.34,716.93 1122.34,689.33 v1(1122.64,689.03) ; D4.3@1122.05,747.24 1122.39,747.59 1122.39,769.71 1130.49,777.8 v1(1130.49,780.51) ; v1(1192.91,3448.82) 1192.91,3476.38 1215.16,3498.62 U2.7@1283.46,3498.62 1345.81,3498.62 1377.31,3467.12 v1@1377.31,3448.62 ; J11.A1@1230.32,856.89 J11.B12@1230.32,925 ; R101.1@1299.21,500 1348.43,500 1351.38,502.95 ; U7.3@1309.06,3242.13 v1(1309.06,3281.5) ; C4.1@1323.23,3397.64 1349.07,3397.64 1376.72,3425.29 v1(1376.72,3448.62) ; v1(1396.91,598.14) 1367.44,598.14 1351.38,582.07 U18.5@1351.38,547.24 1351.38,502.95 ; C82.1@1397.24,488.19 1366.14,488.19 1351.38,502.95 ; v1(1472.05,811.02) C67.1@1472.05,846.46 v1(1472.05,881.89) ; C52.1@1472.44,3228.74 v1(1472.44,3256.8) ; U2.4@1488.19,3598.62 v1(1558.86,3598.62) ; Y1.2@1499.02,498.03 1500,499.02 v1(1500,539.37) ; v1(1529.87,706.05) 1530.43,706.61 1565.87,706.61 U14.48@1565.94,706.69 1616.14,706.69 U14.PAD@1635.83,726.38 ; U14.47@1565.94,726.38 U14.PAD@1635.83,726.38 ; U14.42@1565.94,824.8 U14.PAD@1714.57,824.8 ; U14.41@1565.94,844.49 U14.PAD@1694.88,844.49 ; v1(1570.87,547.24) 1570.87,587.6 Y1.4@1571.85,588.58 ; v1(1586.61,996.06) 1604.17,996.06 1616.14,984.09 U14.36@1616.14,973.43 1616.14,923.23 U14.PAD@1631.89,907.48 ; U14.35@1635.83,973.43 1635.83,911.42 U14.PAD@1631.89,907.48 ; v1(1641.73,548.82) 1642.52,548.03 1782.68,548.03 C57.1@1783.46,547.24 ; v1(1671.23,3400.36) 1671.23,3402.33 1676.07,3407.17 1678.04,3407.17 1700.79,3429.92 1700.79,3488.19 ; R8.1@1671.23,3486.98 1699.57,3486.98 1700.79,3488.19 ; R7.1@1671.23,3573.59 1671.23,3571.62 1700.79,3542.06 1700.79,3488.19 ; v1(1885.83,3059.06) 1886.02,3059.25 1886.02,3086.42 C8.1@1886.22,3086.61 1887.99,3088.39 1887.99,3143.9 U12.2@1889.76,3145.67 v1(1889.76,3181.1) ; v1(1901.73,3444.29) 1916.34,3458.9 U19.4@1916.34,3471.46 ; v1(1925.2,858.27) 1899.61,883.86 U14.22@1882.87,883.86 U14.PAD@1793.31,883.86 ; v1(1937.01,889.76) 1923.23,903.54 U14.23@1882.87,903.54 1812.99,903.54 U14.PAD@1793.31,883.86 ; v1(1992.13,932.68) 1992.32,932.87 2045.08,932.87 U17.2@2045.28,933.07 ; v1(1996.06,519.69) U15.2@2045.28,519.69 ; v1(1996.06,657.48) U16.2@2045.28,657.48 U16.5@2151.57,657.48 U16.5@2151.77,657.28 ; v1(1996.06,798.82) 1997.83,797.05 2043.5,797.05 U13.2@2045.28,795.28 ; C27.1@2133.86,1043.31 2133.86,1021.61 2139.72,1015.75 2330.71,1015.75 J5.1@2370.08,976.38 ; C75.1@2200.59,657.28 v1(2200.79,657.09) ; U14.PAD@1631.89,907.48 U14.PAD@1694.88,844.49 ; U14.PAD@1635.83,726.38 1675.2,765.75 U14.PAD@1724.41,814.96 ; U14.PAD@1694.88,844.49 U14.PAD@1714.57,824.8 ; U14.PAD@1714.57,824.8 U14.PAD@1724.41,814.96 ; U14.PAD@1724.41,814.96 U14.PAD@1793.31,883.86
  L1-TOP w13: U10.4@-4747.05,4312.99 -4714.91,4312.99 v2(-4711.29,4309.38)
  L1-TOP w15: JP3.3@-5502.92,3327.78 JP3.3@-5502.23,3328.48 ; v1@-5443.36,3328.48 v1(-5442.67,3329.17) ; v1(-404.74,1099.2) C1.2@-404.74,1125.59 ; v1(-78.74,1099.2) C2.2@-78.74,1125.59 ; C77.1@838.19,984.25 807.09,984.25 795.28,972.44 795.28,929.13 FB4.2@791.34,925.2 791.34,881.89 811.02,862.2 v1(850.39,862.2)
  L1-TOP w20: v1(-283.77,2359.46) -283.4,2359.09 -238.82,2359.09 -236.22,2356.5 v1(-236.22,2276.57) ; v1(-271.65,2397.64) -236.22,2433.07 v1(-236.22,2526.57)
  other v1: 1625.98,462.2 1964.57,480.31 1724.41,490.55 2200.79,519.29 1748.03,547.24 1834.65,547.24 1712.6,549.61 1976.38,594.49 1212.6,614.17 1479.92,645.67 1212.51,694.46 1479.92,744.09 1952.76,763.78 2200.79,794.88 1405.91,807.09 1082.68,811.02 1013.78,890.94 1230.32,890.94 1403.54,905.51 1472.05,932.09 2200.79,932.68 1403.54,940.94 500.18,942.03 1437.01,945.28 -4244.6,954.78 1929.13,964.96 1472.05,967.52 1135.66,987.32 -4326.77,996.06 1728.74,1023.62 -4220.47,1114.17 -3586.61,1192.91 -3110.24,1244.09 -236.22,1244.09 -3304.83,1262.13 -3551.18,1263.78 -3515.75,1263.78 -2920.25,1303.35 -3110.24,1318.9 -236.22,1318.9 -3480.32,1334.65 -3307.09,1338.58 377.95,1397.64 -3110.24,1409.45 -236.22,1409.45 401.57,1468.5 -3278.52,1475.54 -3401.57,1480.32 -3110.24,1489.17 -236.22,1489.17 948.82,1496.06 -3472.44,1503.94 35.43,1503.94 -66.93,1543.31 1011.81,1551.18 51.18,1555.12 940.94,1555.12 -3277.96,1557.66 -3110.46,1569.72 -236.45,1569.72 346.46,1622.05 1199.39,1624.24 1019.68,1625.98 -3590.55,1657.48 -3110.24,1659.45 -236.22,1659.45 137.8,1677.17 370.08,1696.85 -304.74,1722.49 -61.44,1722.49 -3559.06,1728.35 -3110.24,1739.17 -236.22,1739.17 311.02,1775.59 -411.01,1781.45 -304.74,1781.55 -61.44,1781.55 381.89,1803.15 -3535.43,1807.09 -3110.46,1819.72 -236.45,1819.72 -61.44,1840.6 -411.01,1841.03 -3490.82,1868.23 -2911.03,1898.8 -61.44,1899.66 -3110.24,1909.06 -236.22,1909.06 -3203.51,1921.35 -3228.35,1948.82 -3289.28,1958.42 -3110.24,1972.44 -236.22,1983.86 -397.64,1988.19 -4311.02,2015.75 -3110.24,2031.5 -236.22,2031.5 -3629.92,2039.37 -397.64,2070.87 -411.01,2096.41 -3598.43,2106.3 -3110.24,2106.3 -236.22,2106.3 -3309.45,2116.41 -2916.13,2116.21 -3363.31,2135.98 -2849.04,2155.51 -411.01,2155.46 -304.74,2155.56 -3309.45,2155.78 -3363.31,2175.89 -3309.45,2195.69 -2782.12,2194.88 -3110.24,2196.85 -236.22,2196.85 -411.01,2214.62 -304.74,2214.62 -61.44,2214.62 -3363.31,2215.26 -2715.57,2233.38 -3309.45,2235.06 -3363.31,2254.63 -411.01,2273.67 -304.74,2273.57 -167.7,2273.57 -61.44,2273.67 -3309.45,2274.43 322.83,2275.59 -3110.24,2276.57 -2696.85,2291.34 -3363.31,2294 -3309.45,2313.8 527.96,2319.6 322.83,2330.71 -411.01,2332.73 -167.7,2332.63 -61.44,2332.73 -3363.31,2333.37 -304.74,2333.15 -3309.45,2353.17 -3110.46,2357.12 -3363.31,2372.74 472.44,2381.89 -304.74,2391.68 -167.7,2391.68 -3309.45,2392.54 -411.01,2391.78 -61.44,2391.78 -3363.31,2412.11 1082.68,2425.2 -500.06,2439.01 -3110.24,2446.85 -304.74,2450.74 -167.7,2450.74 413.39,2460.63 460.63,2519.68 -500,2523.62 -3110.24,2526.57 1177.17,2543.31 1098.43,2547.24 984.25,2559.06 -3110.46,2607.12 -236.45,2607.12 1074.8,2625.98 -3110.24,2696.46 -236.22,2696.46 -5625.98,2713.8 -5509.84,2713.8 -5625.98,2766.51 -5509.84,2766.51 -3110.24,2771.26 -236.22,2771.26 -3110.24,2818.9 -236.22,2818.9 -3110.24,2893.7 -236.22,2893.7 -3110.24,2984.25 -236.22,2984.25 500.18,3061.91 -3110.24,3063.98 -236.22,3063.98 -3068.03,3071.75 -5613.32,3105.69 -5526.7,3105.69 -2911.03,3120.89 1637,3132.74 1689.71,3132.74 -3110.46,3144.52 -236.45,3144.52 2020.64,3149.5 898.91,3205.7 965.27,3205.7 1300.48,3205.7 1366.84,3205.7 -3161.42,3216.54 -2857.16,3219.2 -3110.24,3234.25 -236.22,3234.25 2020.64,3236.12 -2911.03,3239 -2771.65,3240.16 1637,3248.88 1689.71,3248.88 -2857.16,3258.57 -2911.03,3278.37 -411.01,3297.19 -3110.24,3313.98 -236.22,3313.98 -304.74,3356.35 -411.01,3356.78 -3110.46,3394.52 -236.45,3394.52 -304.74,3415.4 -2728.35,3437.01 -3039.37,3440.94 -2803.15,3456.69 -3110.24,3483.86 -2811.02,3484.25 -236.22,3483.86 -2267.72,3492.13 -2885.83,3503.94 1849.21,3521.26 -948.82,3543.31 -3110.24,3558.66 -236.22,3558.66 1940.16,3561.02 -2248.03,3566.93 -2991.92,3577.7 -2013.92,3583.51 -1023.62,3586.61 -2681.1,3588.99 -2468.5,3602.36 -2437.01,3602.36 -2405.51,3602.36 -2377.95,3602.36 -1742.55,3604.92 -1702.91,3605.19 -1663.54,3605.19 -1624.17,3605.19 -1584.8,3605.19 -1545.43,3605.19 -1506.06,3605.19 -1466.69,3605.19 -1427.32,3605.19 -1387.95,3605.19 -910.88,3608.6 -2539.37,3625.98 -1220.47,3625.98 -2492.13,3633.86 -2118.11,3645.67 -2232.28,3649.61 -657.48,3649.61 -2972.44,3653.54 -2291.34,3653.54 -1248.03,3653.54 -988.19,3653.54 -921.26,3657.48 -1762.35,3658.79 -1722.71,3659.06 -1683.34,3659.06 -1643.97,3659.06 -1604.6,3659.06 -1565.23,3659.06 -1525.86,3659.06 -1486.49,3659.06 -1447.12,3659.06 -1407.75,3659.06 -720.47,3661.42 -2645.8,3662.66 -797.06,3665.08 -2503.94,3677.17 -972.98,3677.52 -1271.65,3681.1 -2807.09,3688.98 -1299.21,3708.66 -500,3712.6 -2855.04,3717.11 -2120.15,3726.64 -480.32,3748.03 -2771.65,3779.53 -2645.67,3783.46 -2570.87,3783.46 -2059.06,3783.46 -837.34,3784.63 -409.45,3791.34 -4799.88,3793.94 -681.1,3799.21 -2417.32,3822.83 -2830.32,3858.27 -2755.91,3858.27 -2666.18,3858.04 -2566.93,3858.27 -2531.5,3858.27 -2416.18,3858.04 -2335.63,3858.27 -2275.59,3858.27 -2165.35,3858.27 -2102.36,3858.27 -2042.91,3858.27 -1968.11,3858.27 -1878.78,3858.04 -1798.23,3858.27 -1718.5,3858.27 -1628.78,3858.04 -1555.12,3858.27 -1468.5,3858.27 -1377.95,3858.27 -1307.09,3858.27 -1253.41,3858.13 -1180.71,3858.27 -1091.37,3858.04 -1031.5,3858.27 -931.1,3858.27 -841.37,3858.04 -760.83,3858.27 -681.1,3858.27 -590.55,3858.27 -515.75,3858.27 1695.84,3859.27 -778.53,3888.48 1652.54,3902.58 -2253.94,3903.6 -2358.27,3913.39 1861.89,3921.84 -791.06,3934.8 -722.86,3936 1787.32,3945.94 -2787.4,3984.25 -1859.97,4057.48 -1820.6,4057.48 -1781.23,4057.48 -1741.86,4057.48 -1035.43,4062.99 -625.98,4074.8 -2842.52,4078.74 -2885.83,4110.24 -1879.77,4111.34 -1840.4,4111.34 -1801.03,4111.34 -1761.66,4111.34 -2925.2,4133.86 -572.02,4134.75 1775.59,4141.73 -500,4161.42 1846.46,4177.17 1866.14,4228.35 1944.88,4240.16 -5228.35,4562.99 -2124.94,4672.18 -2199.74,4695.81 -4842.52,4870.08 -4803.15,4870.08 -4763.78,4870.08 -4724.41,4870.08 -4685.04,4870.08 -4842.52,4980.32 -4803.15,4980.32 -4763.78,4980.32 -4724.41,4980.32 -4685.04,4980.32 1066.93,5200.79 -4055.12,5228.35 -4141.73,5236.22 1062.99,5274.59 -4574.8,5283.46
  other v2: -3977.59,740.16 -3906.66,740.16 -3878.77,755.91 -3807.84,755.91 -3977.59,834.65 -3906.66,834.65 -3878.77,850.39 -3807.84,850.39 111.99,890.85 139.16,890.85 -3977.59,929.13 -3906.66,929.13 111.99,938.09 139.55,938.09 -3878.77,944.88 -3807.84,944.88 -3977.59,1118.11 -3906.66,1118.11 99.01,1122.78 215.93,1123.13 354.71,1123.13 -3878.77,1133.86 -3977.59,1212.6 -3906.66,1212.6 -3878.77,1228.35 -3807.84,1228.35 680.68,1265.75 751.61,1265.75 779.5,1281.5 850.43,1281.5 110.6,1283.46 162.6,1283.46 253.31,1283.46 305.31,1283.46 392.09,1283.46 444.09,1283.46 -3977.59,1307.09 -3906.66,1307.09 110.6,1316.39 162.6,1316.39 253.31,1316.39 305.31,1316.39 392.09,1316.39 444.09,1316.39 -3878.77,1322.83 -3807.84,1322.83 680.68,1360.24 751.61,1360.24 779.5,1375.98 850.43,1375.98 751.61,1454.72 779.5,1470.47 850.43,1470.47 680.68,1643.7 751.61,1643.7 779.5,1659.45 850.43,1659.45 -3977.59,1724.41 -3906.66,1724.41 680.68,1738.19 751.61,1738.19 -3878.77,1740.16 -3807.84,1740.16 779.5,1753.94 850.43,1753.94 -3977.59,1818.9 -3906.66,1818.9 680.68,1832.68 751.61,1832.68 -3878.77,1834.65 -3807.84,1834.65 779.5,1848.43 850.43,1848.43 -3977.59,1913.39 -3906.66,1913.39 -3878.77,1929.13 -3807.84,1929.13 -4311.02,1976.38 -3977.59,2102.36 -3906.66,2102.36 -3878.77,2118.11 -3977.59,2196.85 -3906.66,2196.85 -3878.77,2212.6 -3807.84,2212.6 680.68,2250 751.61,2250 779.5,2265.75 850.43,2265.75 -3977.59,2291.34 -3906.66,2291.34 -3878.77,2307.09 -3807.84,2307.09 680.68,2344.49 751.61,2344.49 779.5,2360.24 850.43,2360.24 751.61,2438.98 779.5,2454.72 850.43,2454.72 -5123.44,2483.91 -5071.44,2483.91 -4980.72,2483.91 -4928.72,2483.91 -4841.95,2483.91 -4789.95,2483.91 -4493.52,2483.91 -4441.52,2483.91 -4350.8,2483.91 -4298.8,2483.91 -4212.02,2483.91 -4160.02,2483.91 -5123.44,2516.83 -5071.44,2516.83 -4980.72,2516.83 -4928.72,2516.83 -4841.95,2516.83 -4789.95,2516.83 -4493.52,2516.83 -4441.52,2516.83 -4350.8,2516.83 -4298.8,2516.83 -4212.02,2516.83 -4160.02,2516.83 680.68,2627.95 751.61,2627.95 779.5,2643.7 850.43,2643.7 -5135.03,2677.52 -5018.11,2677.17 -4879.33,2677.17 -4505.11,2677.52 -4388.19,2677.17 -4249.41,2677.17 110.6,2687.55 162.6,2687.55 253.31,2687.55 305.31,2687.55 392.09,2687.55 444.09,2687.55 110.6,2720.47 162.6,2720.47 253.31,2720.47 305.31,2720.47 392.09,2720.47 444.09,2720.47 680.68,2722.44 751.61,2722.44 779.5,2738.19 850.43,2738.19 680.68,2816.93 751.61,2816.93 779.5,2832.68 850.43,2832.68 -4733.86,2858.27 -4103.94,2858.27 -5122.05,2862.2 -5094.49,2862.2 -4492.13,2862.2 -4464.57,2862.2 99.01,2881.16 215.93,2880.8 354.71,2880.8 -5122.05,2909.45 -5094.88,2909.45 -4492.13,2909.45 -4464.96,2909.45 111.99,3065.84 139.55,3065.84 111.99,3113.09 139.16,3113.09 -4647.2,3604.94 -4612.2,3604.94 -4724.2,3605.94 -4688.2,3605.94 -4572.2,3605.94 -4535.2,3605.94 -4461.2,3605.94 -4493.2,3606.94 -4493.2,3633.2 -4724.2,3634.2 -4688.2,3634.2 -4572.2,3634.2 -4535.2,3634.2 -4461.2,3634.2 -4647.2,3635.2 -4612.2,3635.2 -4511.62,3676.15 -4467.62,3676.15 -4420.41,3676.15 -4376.41,3676.15 -4329.25,3676.24 -4285.25,3676.24 -4660.17,3684.59 -4627.49,3684.59 -4593.17,3684.59 -4553.27,3701.27 -4511.2,3706.94 -4467.2,3706.94 -4419.99,3706.94 -4375.99,3706.94 -4328.83,3707.02 -4284.83,3707.02 2362.26,3784.42 2523.62,3787.4 2362.2,3819.66 2132.05,3834.6 -4596.27,3850.36 2362.26,3855.42 2192.27,3885.23 2532.14,3885.54 -4596.14,3885.8 2362.26,3929.42 2306.15,3944.6 2418.26,3944.6 2192.27,3956.09 2532.14,3956.41 2362.26,3985.42 2191.81,4007.59 2306.15,4015.46 2418.26,4015.46 2362.26,4044.42 2531.38,4064.63 2315.5,4067.74 2187.28,4071.27 2413.27,4074.52 -4732.25,4081.87 -4700.43,4081.87 2362.26,4095.42 -4716.34,4107.87 2531.38,4123.69 2413.27,4131.33 2187.28,4133.57 -4732.25,4133.87 -4700.43,4133.87 -4732.25,4172.87 -4700.43,4172.87 2362.15,4178.89 2532.14,4180.82 2179.27,4185.71 2413.27,4190.39 -4716.34,4198.87 -4732.25,4224.87 -4700.43,4224.87 2187.28,4239.56 2418.26,4239.56 2362.2,4244.09 2532.14,4251.68 -4655.67,4252.99 -4630.13,4254.29 2362.2,4299.21 2177.17,4307.09 -4669.29,4309.38 -4627.29,4309.38 2418.26,4310.42 -4793.25,4323.79 2362.2,4326.77 -4711.29,4351.38 -4669.29,4351.38 -4627.29,4351.38 2192.27,4369.48 -4711.29,4393.38 -4669.29,4393.38 -4627.29,4393.38 2362.15,4418.89 2362.2,4454.66 -4594.17,4473.87 2362.15,4489.89 -4563.08,4511.87 -4531.25,4511.87 -4547.17,4537.87 -4563.08,4563.87 -4531.25,4563.87 -4103.94,5277.15 -2253.54,5277.15 -324.41,5277.15 1525.99,5277.15 -4663.59,5336.61 -4596.41,5336.61 -4411.59,5336.61 -4344.41,5336.61 -4285.59,5336.61 -4218.41,5336.61 -2498.2,5336.61 -2431.01,5336.61 966.43,5336.61 1033.61,5336.61 1218.43,5336.61 1285.61,5336.61 -793.37,5457.68 -730.37,5457.68 -667.37,5457.68 1281.43,5461.41 1348.61,5461.41 -4762.18,5511.76 -4691.18,5511.76 -4617.18,5511.76 -4561.18,5511.76 -4502.18,5511.76 -4451.18,5511.76 -2911.79,5511.76 -2840.79,5511.76 -2766.79,5511.76 -2710.79,5511.76 -2651.79,5511.76 -2600.79,5511.76 -982.65,5511.76 -911.65,5511.76 -837.65,5511.76 -781.65,5511.76 -722.65,5511.76 -671.65,5511.76 867.74,5511.76 938.74,5511.76 1012.74,5511.76 1068.74,5511.76 1127.74,5511.76 1178.74,5511.76 -4726.95,5511.81 -4367.72,5511.87 -4316.72,5511.87 -4257.72,5511.87 -4201.72,5511.87 -4127.72,5511.87 -4091.95,5511.81 -4056.72,5511.87 -2876.56,5511.81 -2517.32,5511.87 -2466.32,5511.87 -2407.32,5511.87 -2351.32,5511.87 -2277.32,5511.87 -2206.32,5511.87 -947.42,5511.81 -588.19,5511.87 -537.19,5511.87 -478.19,5511.87 -422.19,5511.87 -348.19,5511.87 -312.42,5511.81 -277.19,5511.87 902.97,5511.81 1262.21,5511.87 1313.21,5511.87 1372.21,5511.87 1428.21,5511.87 1502.21,5511.87 1537.97,5511.81 1573.21,5511.87 -2539.37,5555.12 -748.03,5555.12 -4411.59,5562.21 -4344.41,5562.21 -4285.59,5562.21 -4218.41,5562.21 -2494.01,5562.21 -2435.2,5562.21 -2368.01,5562.21 -884.06,5562.21 -816.88,5562.21 -632.06,5562.21 -564.88,5562.21 -506.06,5562.21 -438.88,5562.21 966.43,5562.21 1033.61,5562.21 1218.33,5562.21 1285.51,5562.21 1344.33,5562.21 1411.51,5562.21 -4604.35,5564.55 -4541.35,5564.55 -2753.95,5564.55 -2690.95,5564.55 1088.57,5564.55 -4478.4,5565.94 -2628,5565.94 -698.87,5565.94 -4059.06,5633.86 -4572.9,5683.28 -4509.9,5683.28 -4446.9,5683.28 -2722.5,5683.28 -2659.5,5683.28 -2596.5,5683.28 -730.37,5683.28 -667.37,5683.28 1183.02,5683.28 -4348.49,5684.51 -4281.31,5684.51 -2498.1,5684.51 -2430.91,5684.51 -2372.1,5684.51 -2304.91,5684.51 -568.96,5684.51 -501.78,5684.51 -442.96,5684.51 -375.78,5684.51 1281.43,5684.51 1348.61,5684.51 1407.43,5684.51 1474.61,5684.51
EECLK: R100.1 U14.44 U18.2 | length 382.1
  L1-TOP w4.96: R100.1@1299.21,610.24 1330.71,610.24 1401.57,681.1 U18.2@1401.57,721.46 ; U18.2@1402.56,720.47 U18.2@1401.57,721.46 ; U14.44@1565.94,785.43 1545.16,785.43 1537.1,777.38 1444.43,777.38 1431.9,764.84 1414.58,764.84 1401.57,751.84 U18.2@1401.57,721.46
